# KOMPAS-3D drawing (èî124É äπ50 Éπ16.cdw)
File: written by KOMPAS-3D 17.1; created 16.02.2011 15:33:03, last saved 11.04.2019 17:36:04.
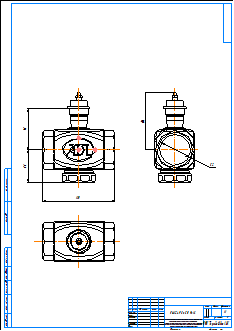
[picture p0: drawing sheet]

Title block, sheet 1: name: КМ124Р Ду50 Ру16; material: Внимание! Данный продукт является объектом авторского права ООО «Торговый Дом АДЛ». / Запрещается изменение, копирование, распространение / (в том числе путем копирования на другие сайты и ресурсы в Интернете) / или любое иное использование информации и объектов без предварительного / согласия правообладателя (ООО «Торговый Дом АДЛ»).; scale: 1:1; sheets: 1; organisation: ООО "Торговый дом АДЛ"; sheet format: A2; stored path: \\adlc.lan\data\АДЛ_ПКД\3D-модели\ADL production\Клапаны ГРАНРЕГ\Двухходовой клапан KM124P\KOMPAS 2D\КМ124Р Ду50 Ру16.cdw

Views: Спереди 1, Проекционный вид 2, Проекционный вид 3
Dimensions and other numbers on the sheet: 130; 58; 75; 104; 1:1; 1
